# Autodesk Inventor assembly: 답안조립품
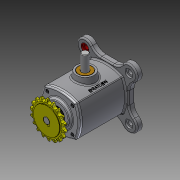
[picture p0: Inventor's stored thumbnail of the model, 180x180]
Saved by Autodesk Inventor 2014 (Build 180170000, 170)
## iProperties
Created: 2016-05
Part Number: 답안조립품
Document SubType Name: Assembly
Designer: Administrator
Author: Administrator
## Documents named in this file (11)
- C:\Users\Administrator\Desktop\460507V1011\답안조립품.iam
- C:\Users\Administrator\Desktop\460507V1011\1-본체.ipt
- C:\Users\Administrator\Desktop\460507V1011\M4x0.7x12.ipt
- C:\Users\Administrator\Desktop\460507V1011\베어링-6203.ipt
- C:\Users\Administrator\Desktop\460507V1011\부시.ipt
- C:\Users\Administrator\Desktop\460507V1011\스프로킷.ipt
- C:\Users\Administrator\Desktop\460507V1011\슬라이더.ipt
- C:\Users\Administrator\Desktop\460507V1011\오일실.ipt
- C:\Users\Administrator\Desktop\460507V1011\커버.ipt
- C:\Users\Administrator\Desktop\460507V1011\키5x5.ipt
- C:\Users\Administrator\Desktop\460507V1011\편심축.ipt
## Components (9 placed, 2 different names)
1. 1-본체:1
2. M4x0.7x12:2
3. M4x0.7x12:3
4. M4x0.7x12:4
5. M4x0.7x12:5
6. M4x0.7x12:1
7. M4x0.7x12:6
8. M4x0.7x12:7
9. M4x0.7x12:8
## Named parameters: d2_d0 = 0, d3_d1 = 0
